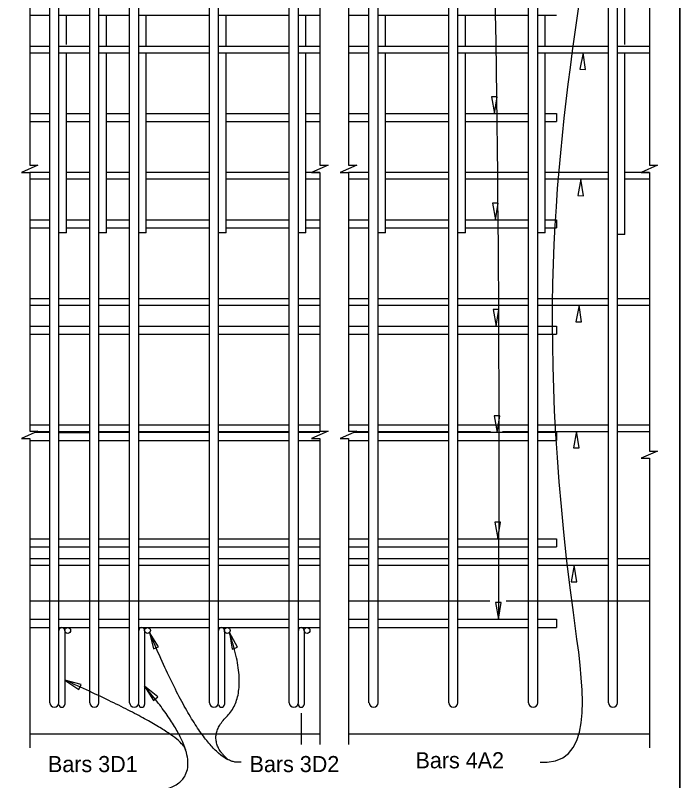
# Model space of a CAD drawing. Extents: x 0 to 20.5, y 0 to 12.9.
# Drawn here: x 16.322 to 20.485, y 4.445 to 9.244 of the extents above; entities that cross this region are included whole.
import ezdxf

# ---------------------------------------------------------------- set-up
doc = ezdxf.new("R2010")
doc.units = 0
for name, color, linetype in [('ActivePts-ConstElements', 7, 'Continuous'), ('BeamConc', 7, 'Continuous'), ('BeamConc_h', 7, 'Continuous'), ('Dimension', 7, 'Continuous'), ('Miscellaneous1', 7, 'Continuous'), ('Rebar', 7, 'Continuous'), ('TextStructures', 7, 'Continuous')]:
    doc.layers.add(name, color=color, linetype=linetype)

msp = doc.modelspace()

# ---------------------------------------------------------------- linework, layer by layer
at = {"layer": 'ActivePts-ConstElements'}
msp.add_lwpolyline([(-0.0403, -0.0256), (20.485, -0.0256), (20.485, 12.9475), (-0.0403, 12.9475)], close=True, dxfattribs=at)
at = {"layer": 'BeamConc'}
for p, q in [((16.4116, 4.739), (18.2295, 4.739)), ((18.4095, 4.739), (20.2953, 4.739))]:
    msp.add_line(p, q, dxfattribs=at)
at = {"layer": 'BeamConc_h'}
for p, q in [((16.4116, 5.5723), (18.2295, 5.5723)), ((18.4095, 5.5723), (19.2946, 5.5723)), ((19.3975, 5.5723), (20.2953, 5.5723))]:
    msp.add_line(p, q, dxfattribs=at)
at = {"layer": 'Dimension'}
msp.add_line((18.1135, 4.8686), (18.1135, 4.6717), dxfattribs=at)
for points in [[(16.4116, 10.0723), (16.4116, 8.3039), (16.4633, 8.3039), (16.36, 8.2589), (16.4116, 8.2589), (16.4116, 6.6365), (16.4633, 6.6365), (16.36, 6.5915), (16.4116, 6.5915), (16.4116, 4.6506)], [(18.2295, 10.0723), (18.2295, 8.3039), (18.2812, 8.3039), (18.1778, 8.2589), (18.2295, 8.2589), (18.2295, 6.6365), (18.2812, 6.6365), (18.1778, 6.5915), (18.2295, 6.5915), (18.2295, 4.6717)], [(18.4095, 10.0723), (18.4095, 8.3039), (18.4612, 8.3039), (18.3579, 8.2589), (18.4095, 8.2589), (18.4095, 6.6365), (18.4612, 6.6365), (18.3579, 6.5915), (18.4095, 6.5915), (18.4095, 4.6717)], [(20.2953, 10.0723), (20.2953, 8.3039), (20.347, 8.3039), (20.2437, 8.2589), (20.2953, 8.2589), (20.2953, 6.5115), (20.347, 6.5115), (20.2437, 6.4665), (20.2953, 6.4665), (20.2953, 4.6506)]]:
    msp.add_lwpolyline(points, dxfattribs=at)
for points in [[(19.8792, 9.0099), (19.8601, 8.906), (19.8953, 8.9055)], [(19.3235, 8.6296), (19.3404, 8.7339), (19.3051, 8.7336)], [(19.8656, 8.2178), (19.8465, 8.1139), (19.8818, 8.1134)], [(19.3313, 7.9628), (19.3482, 8.067), (19.3129, 8.0668)], [(19.3355, 7.2956), (19.3525, 7.3999), (19.3172, 7.3996)], [(19.8543, 7.4259), (19.8352, 7.3221), (19.8704, 7.3216)], [(19.3403, 6.6295), (19.3572, 6.7338), (19.322, 6.7335)], [(19.8387, 6.6364), (19.8196, 6.5325), (19.8549, 6.532)], [(19.3451, 5.9629), (19.362, 6.0671), (19.3267, 6.0669)], [(19.8246, 5.7963), (19.8055, 5.6925), (19.8408, 5.692)], [(19.3494, 5.4578), (19.3664, 5.562), (19.3311, 5.5618)], [(17.1629, 5.3745), (17.1867, 5.2716), (17.2193, 5.2852)], [(17.6629, 5.3745), (17.6802, 5.2703), (17.7135, 5.2818)], [(16.6318, 5.0758), (16.7197, 5.0172), (16.734, 5.0494)], [(17.1318, 5.0372), (17.1876, 4.9476), (17.214, 4.9709)]]:
    msp.add_lwpolyline(points, close=True, dxfattribs=at)
for points in [[(19.5169, 10.7039), (19.4625, 10.7051), (19.3121, 10.2105), (19.3494, 5.4578)], [(19.6115, 4.5619), (19.6547, 4.5619), (19.819, 5.4995), (19.8873, 9.5318)]]:
    msp.add_spline(points, degree=3, dxfattribs=at)
for points in [[(17.7362, 4.5622), (17.5173, 4.5252), (17.1629, 5.3745)], [(17.6567, 4.5757), (17.5049, 4.7071), (17.7938, 4.995), (17.6629, 5.3745)], [(17.3904, 4.6335), (17.3739, 4.7442), (16.6318, 5.0758)], [(17.0406, 4.3694), (17.7177, 4.3524), (17.1318, 5.0372)]]:
    msp.add_open_spline(points, degree=2, dxfattribs=at)
at = {"layer": 'Miscellaneous1'}
msp.add_lwpolyline([(0, 12.9475), (20.485, 12.9475), (20.485, 0), (0, 0)], close=True, dxfattribs=at)
at = {"layer": 'Rebar'}
for p, q in [((16.5953, 4.9343), (16.5953, 10.4187)), ((16.8453, 4.9343), (16.8453, 10.4187)), ((17.0953, 4.9343), (17.0953, 10.4187)), ((17.5953, 4.9343), (17.5953, 10.4187)), ((18.0953, 4.9343), (18.0953, 10.4187)), ((18.5953, 4.9343), (18.5953, 10.4187)), ((19.0953, 4.9343), (19.0953, 10.4187)), ((19.5953, 4.9343), (19.5953, 10.4187)), ((20.0953, 4.9343), (20.0953, 10.4187)), ((20.1422, 9.0619), (20.1422, 9.8475)), ((16.538, 4.9343), (16.538, 9.5318)), ((16.788, 4.9343), (16.788, 9.5318)), ((17.038, 4.9343), (17.038, 9.5318)), ((17.538, 4.9343), (17.538, 9.5318)), ((18.038, 4.9343), (18.038, 9.5318)), ((18.538, 4.9343), (18.538, 9.5318)), ((19.038, 4.9343), (19.038, 9.5318)), ((19.538, 4.9343), (19.538, 9.5318)), ((20.038, 4.9343), (20.038, 9.5318)), ((16.4116, 9.2443), (16.538, 9.2443)), ((16.5953, 9.2443), (16.788, 9.2443)), ((16.6422, 9.0619), (16.6422, 9.2443)), ((16.8453, 9.2443), (17.038, 9.2443)), ((16.8922, 9.0515), (16.8922, 9.2443)), ((17.0953, 9.2443), (17.538, 9.2443)), ((17.1422, 9.0515), (17.1422, 9.2443)), ((17.5953, 9.2443), (18.038, 9.2443)), ((17.6422, 9.0515), (17.6422, 9.2443)), ((18.0953, 9.2443), (18.2295, 9.2443)), ((18.1422, 9.0515), (18.1422, 9.2443)), ((18.4095, 9.2443), (18.538, 9.2443)), ((18.5953, 9.2443), (19.038, 9.2443)), ((18.6422, 9.0515), (18.6422, 9.2443)), ((19.0953, 9.2443), (19.538, 9.2443)), ((19.1422, 9.0515), (19.1422, 9.2443)), ((19.5953, 9.2443), (19.7125, 9.2443)), ((19.6422, 9.0515), (19.6422, 9.2443)), ((16.4116, 9.0515), (16.538, 9.0515)), ((16.5953, 9.0515), (16.788, 9.0515)), ((16.8453, 9.0515), (17.038, 9.0515)), ((17.0953, 9.0515), (17.538, 9.0515)), ((17.5953, 9.0515), (18.038, 9.0515)), ((18.0953, 9.0515), (18.2295, 9.0515)), ((18.4095, 9.0515), (18.538, 9.0515)), ((18.5953, 9.0515), (19.038, 9.0515)), ((19.0953, 9.0515), (19.538, 9.0515)), ((19.5953, 9.0515), (20.038, 9.0515)), ((20.0953, 9.0515), (20.2953, 9.0515)), ((16.4116, 9.0099), (16.538, 9.0099)), ((16.5953, 9.0099), (16.788, 9.0099)), ((16.6422, 7.8796), (16.6422, 9.0099)), ((16.8453, 9.0099), (17.038, 9.0099)), ((16.8922, 7.8796), (16.8922, 9.0099)), ((17.0953, 9.0099), (17.538, 9.0099)), ((17.1422, 7.8796), (17.1422, 9.0099)), ((17.5953, 9.0099), (18.038, 9.0099)), ((17.6422, 7.8796), (17.6422, 9.0099)), ((18.0953, 9.0099), (18.2295, 9.0099)), ((18.1422, 7.8796), (18.1422, 9.0099)), ((18.4095, 9.0099), (18.538, 9.0099)), ((18.5953, 9.0099), (19.038, 9.0099)), ((18.6422, 7.8796), (18.6422, 9.0099)), ((19.0953, 9.0099), (19.538, 9.0099)), ((19.1422, 7.8796), (19.1422, 9.0099)), ((19.5953, 9.0099), (20.038, 9.0099)), ((19.6422, 7.8796), (19.6422, 9.0099)), ((20.0953, 9.0099), (20.2953, 9.0099)), ((20.1422, 7.8692), (20.1422, 9.0099)), ((16.4116, 8.6296), (16.538, 8.6296)), ((16.6422, 8.6296), (16.788, 8.6296)), ((16.8922, 8.6296), (17.038, 8.6296)), ((17.1422, 8.6296), (17.538, 8.6296)), ((17.6422, 8.6296), (18.038, 8.6296)), ((18.1422, 8.6296), (18.2295, 8.6296)), ((18.4095, 8.6296), (18.538, 8.6296)), ((18.6422, 8.6296), (19.038, 8.6296)), ((19.1422, 8.6296), (19.538, 8.6296)), ((19.6422, 8.6296), (19.7125, 8.6296)), ((19.7125, 8.6296), (19.7125, 8.5776)), ((16.4116, 8.5776), (16.538, 8.5776)), ((16.6422, 8.5776), (16.788, 8.5776)), ((16.8922, 8.5776), (17.038, 8.5776)), ((17.1422, 8.5776), (17.538, 8.5776)), ((17.6422, 8.5776), (18.038, 8.5776)), ((18.1422, 8.5776), (18.2295, 8.5776)), ((18.4095, 8.5776), (18.538, 8.5776)), ((18.6422, 8.5776), (19.038, 8.5776)), ((19.1422, 8.5776), (19.538, 8.5776)), ((19.6422, 8.5776), (19.7125, 8.5776)), ((16.4116, 8.2598), (16.538, 8.2598)), ((16.6422, 8.2598), (16.788, 8.2598)), ((16.8922, 8.2598), (17.038, 8.2598)), ((17.1422, 8.2598), (17.538, 8.2598)), ((17.6422, 8.2598), (18.038, 8.2598)), ((18.1422, 8.2598), (18.2295, 8.2598)), ((18.4095, 8.2598), (18.538, 8.2598)), ((18.6422, 8.2598), (19.038, 8.2598)), ((19.1422, 8.2598), (19.538, 8.2598)), ((19.6422, 8.2598), (20.038, 8.2598)), ((20.1422, 8.2598), (20.2953, 8.2598)), ((16.4116, 8.2182), (16.538, 8.2182)), ((16.6422, 8.2182), (16.788, 8.2182)), ((16.8922, 8.2182), (17.038, 8.2182)), ((17.1422, 8.2182), (17.538, 8.2182)), ((17.6422, 8.2182), (18.038, 8.2182)), ((18.1422, 8.2182), (18.2295, 8.2182)), ((18.4095, 8.2182), (18.538, 8.2182)), ((18.6422, 8.2182), (19.038, 8.2182)), ((19.1422, 8.2182), (19.538, 8.2182)), ((19.6422, 8.2182), (20.038, 8.2182)), ((20.1422, 8.2182), (20.2953, 8.2182)), ((16.4116, 7.9629), (16.538, 7.9629)), ((16.6422, 7.9629), (16.788, 7.9629)), ((16.8922, 7.9629), (17.038, 7.9629)), ((17.1422, 7.9629), (17.538, 7.9629)), ((17.6422, 7.9629), (18.038, 7.9629)), ((18.1422, 7.9629), (18.2295, 7.9629)), ((18.4095, 7.9629), (18.538, 7.9629)), ((18.6422, 7.9629), (19.038, 7.9629)), ((19.1422, 7.9629), (19.538, 7.9629)), ((19.6422, 7.9629), (19.7125, 7.9629)), ((19.7125, 7.9629), (19.7125, 7.9109)), ((16.4116, 7.9109), (16.538, 7.9109)), ((16.6422, 7.8796), (16.5953, 7.8796)), ((16.6422, 7.9109), (16.788, 7.9109)), ((16.8922, 7.8796), (16.8453, 7.8796)), ((16.8922, 7.9109), (17.038, 7.9109)), ((17.1422, 7.8796), (17.0953, 7.8796)), ((17.1422, 7.9109), (17.538, 7.9109)), ((17.6422, 7.8796), (17.5953, 7.8796)), ((17.6422, 7.9109), (18.038, 7.9109)), ((18.1422, 7.8796), (18.0953, 7.8796)), ((18.1422, 7.9109), (18.2295, 7.9109)), ((18.4095, 7.9109), (18.538, 7.9109)), ((18.6422, 7.8796), (18.5953, 7.8796)), ((18.6422, 7.9109), (19.038, 7.9109)), ((19.1422, 7.8796), (19.0953, 7.8796)), ((19.1422, 7.9109), (19.538, 7.9109)), ((19.6422, 7.8796), (19.5953, 7.8796)), ((19.6422, 7.9109), (19.7125, 7.9109)), ((20.1422, 7.8692), (20.0953, 7.8692)), ((16.4116, 7.4681), (16.538, 7.4681)), ((16.5953, 7.4681), (16.788, 7.4681)), ((16.8453, 7.4681), (17.038, 7.4681)), ((17.0953, 7.4681), (17.538, 7.4681)), ((17.5953, 7.4681), (18.038, 7.4681)), ((18.0953, 7.4681), (18.2295, 7.4681)), ((18.4095, 7.4681), (18.538, 7.4681)), ((18.5953, 7.4681), (19.038, 7.4681)), ((19.0953, 7.4681), (19.538, 7.4681)), ((19.5953, 7.4681), (20.038, 7.4681)), ((20.0953, 7.4681), (20.2953, 7.4681)), ((16.4116, 7.4265), (16.538, 7.4265)), ((16.5953, 7.4265), (16.788, 7.4265)), ((16.8453, 7.4265), (17.038, 7.4265)), ((17.0953, 7.4265), (17.538, 7.4265)), ((17.5953, 7.4265), (18.038, 7.4265)), ((18.0953, 7.4265), (18.2295, 7.4265)), ((18.4095, 7.4265), (18.538, 7.4265)), ((18.5953, 7.4265), (19.038, 7.4265)), ((19.0953, 7.4265), (19.538, 7.4265)), ((19.5953, 7.4265), (20.038, 7.4265)), ((20.0953, 7.4265), (20.2953, 7.4265)), ((16.4116, 7.2962), (16.538, 7.2962)), ((16.5953, 7.2962), (16.788, 7.2962)), ((16.8453, 7.2962), (17.038, 7.2962)), ((17.0953, 7.2962), (17.538, 7.2962)), ((17.5953, 7.2962), (18.038, 7.2962)), ((18.0953, 7.2962), (18.2295, 7.2962)), ((18.4095, 7.2962), (18.538, 7.2962)), ((18.5953, 7.2962), (19.038, 7.2962)), ((19.0953, 7.2962), (19.538, 7.2962)), ((19.5953, 7.2962), (19.7125, 7.2962)), ((19.7125, 7.2962), (19.7125, 7.2442)), ((16.4116, 7.2442), (16.538, 7.2442)), ((16.5953, 7.2442), (16.788, 7.2442)), ((16.8453, 7.2442), (17.038, 7.2442)), ((17.0953, 7.2442), (17.538, 7.2442)), ((17.5953, 7.2442), (18.038, 7.2442)), ((18.0953, 7.2442), (18.2295, 7.2442)), ((18.4095, 7.2442), (18.538, 7.2442)), ((18.5953, 7.2442), (19.038, 7.2442)), ((19.0953, 7.2442), (19.538, 7.2442)), ((19.5953, 7.2442), (19.7125, 7.2442)), ((16.4116, 6.6764), (16.538, 6.6764)), ((16.5953, 6.6764), (16.788, 6.6764)), ((16.8453, 6.6764), (17.038, 6.6764)), ((17.0953, 6.6764), (17.538, 6.6764)), ((17.5953, 6.6764), (18.038, 6.6764)), ((18.0953, 6.6764), (18.2295, 6.6764)), ((18.4095, 6.6764), (18.538, 6.6764)), ((18.5953, 6.6764), (19.038, 6.6764)), ((19.0953, 6.6764), (19.538, 6.6764)), ((19.5953, 6.6764), (20.038, 6.6764)), ((20.0953, 6.6764), (20.2953, 6.6764)), ((16.449, 6.6296), (16.538, 6.6296)), ((16.4603, 6.6348), (16.538, 6.6348)), ((16.5953, 6.6348), (16.788, 6.6348)), ((16.5953, 6.6295), (16.788, 6.6295)), ((16.8453, 6.6348), (17.038, 6.6348)), ((16.8453, 6.6296), (17.038, 6.6296)), ((17.0953, 6.6348), (17.538, 6.6348)), ((17.0953, 6.6296), (17.538, 6.6296)), ((17.5953, 6.6348), (18.038, 6.6348)), ((17.5953, 6.6296), (18.038, 6.6296)), ((18.0953, 6.6348), (18.2295, 6.6348)), ((18.0953, 6.6296), (18.2295, 6.6296)), ((18.447, 6.6296), (18.538, 6.6296)), ((18.4582, 6.6348), (18.538, 6.6348)), ((18.5953, 6.6348), (19.038, 6.6348)), ((18.5953, 6.6296), (19.038, 6.6296)), ((19.0953, 6.6348), (19.2997, 6.6348)), ((19.0953, 6.6296), (19.538, 6.6296)), ((19.3742, 6.6348), (19.538, 6.6348)), ((19.5953, 6.6348), (20.038, 6.6348)), ((19.5953, 6.6296), (19.7125, 6.6296)), ((19.7125, 6.6296), (19.7125, 6.5775)), ((20.0953, 6.6348), (20.2953, 6.6348)), ((16.4116, 6.5774), (16.538, 6.5774)), ((16.5953, 6.5775), (16.788, 6.5775)), ((16.8453, 6.5775), (17.038, 6.5775)), ((17.0953, 6.5775), (17.538, 6.5775)), ((17.5953, 6.5775), (18.038, 6.5775)), ((18.0953, 6.5775), (18.2295, 6.5775)), ((18.4095, 6.5775), (18.538, 6.5775)), ((18.5953, 6.5775), (19.038, 6.5775)), ((19.0953, 6.5775), (19.538, 6.5775)), ((19.5953, 6.5775), (19.7125, 6.5775)), ((16.4116, 5.9628), (16.538, 5.9628)), ((16.5953, 5.9628), (16.788, 5.9628)), ((16.8453, 5.9628), (17.038, 5.9628)), ((17.0953, 5.9628), (17.538, 5.9628)), ((17.5953, 5.9628), (18.038, 5.9628)), ((18.0953, 5.9628), (18.2295, 5.9628)), ((18.4095, 5.9628), (18.538, 5.9628)), ((18.5953, 5.9628), (19.038, 5.9628)), ((19.0953, 5.9628), (19.538, 5.9628)), ((19.5953, 5.9628), (19.7125, 5.9628)), ((19.7125, 5.9628), (19.7125, 5.9108)), ((16.4116, 5.9108), (16.538, 5.9108)), ((16.5953, 5.9108), (16.788, 5.9108)), ((16.8453, 5.9108), (17.038, 5.9108)), ((17.0953, 5.9108), (17.538, 5.9108)), ((17.5953, 5.9108), (18.038, 5.9108)), ((18.0953, 5.9108), (18.2295, 5.9108)), ((18.4095, 5.9108), (18.538, 5.9108)), ((18.5953, 5.9108), (19.038, 5.9108)), ((19.0953, 5.9108), (19.538, 5.9108)), ((19.5953, 5.9108), (19.7125, 5.9108)), ((16.4116, 5.838), (16.538, 5.838)), ((16.5953, 5.838), (16.788, 5.838)), ((16.8453, 5.838), (17.038, 5.838)), ((17.0953, 5.838), (17.538, 5.838)), ((17.5953, 5.838), (18.038, 5.838)), ((18.0953, 5.838), (18.2295, 5.838)), ((18.4095, 5.838), (18.538, 5.838)), ((18.5953, 5.838), (19.038, 5.838)), ((19.0953, 5.838), (19.538, 5.838)), ((19.5953, 5.838), (20.038, 5.838)), ((20.0953, 5.838), (20.2953, 5.838)), ((16.4116, 5.7963), (16.538, 5.7963)), ((16.5953, 5.7963), (16.788, 5.7963)), ((16.8453, 5.7963), (17.038, 5.7963)), ((17.0953, 5.7963), (17.538, 5.7963)), ((17.5953, 5.7963), (18.038, 5.7963)), ((18.0953, 5.7963), (18.2295, 5.7963)), ((18.4095, 5.7963), (18.538, 5.7963)), ((18.5953, 5.7963), (19.038, 5.7963)), ((19.0953, 5.7963), (19.538, 5.7963)), ((19.5953, 5.7963), (20.038, 5.7963)), ((20.0953, 5.7963), (20.2953, 5.7963)), ((16.4116, 5.4577), (16.538, 5.4577)), ((16.5953, 5.4577), (16.788, 5.4577)), ((16.8453, 5.4577), (17.038, 5.4577)), ((17.0953, 5.4577), (17.538, 5.4577)), ((17.5953, 5.4577), (18.038, 5.4577)), ((18.0953, 5.4577), (18.2295, 5.4577)), ((18.4095, 5.4577), (18.538, 5.4577)), ((18.5953, 5.4577), (19.038, 5.4577)), ((19.0953, 5.4577), (19.538, 5.4577)), ((19.5953, 5.4577), (19.7125, 5.4577)), ((19.7125, 5.4577), (19.7125, 5.4057)), ((16.4116, 5.4057), (16.538, 5.4057)), ((16.5953, 5.4057), (16.788, 5.4057)), ((16.6318, 5.3874), (16.6318, 4.9239)), ((16.8453, 5.4057), (17.038, 5.4057)), ((17.0953, 5.4057), (17.538, 5.4057)), ((17.1318, 5.3874), (17.1318, 4.9239)), ((17.5953, 5.4057), (18.038, 5.4057)), ((17.6318, 5.3874), (17.6318, 4.9239)), ((18.0953, 5.4057), (18.2295, 5.4057)), ((18.1318, 5.3874), (18.1318, 4.9239)), ((18.4095, 5.4057), (18.538, 5.4057)), ((18.5953, 5.4057), (19.038, 5.4057)), ((19.0953, 5.4057), (19.538, 5.4057)), ((19.5953, 5.4057), (19.7125, 5.4057))]:
    msp.add_line(p, q, dxfattribs=at)
for centre in [(16.65, 5.3874), (17.15, 5.3874), (17.65, 5.3874), (18.15, 5.3874)]:
    msp.add_circle(centre, 0.0182, dxfattribs=at)
for centre, radius, start, end in [((16.6135, 5.3874), 0.0182, 0, 180), ((17.1135, 5.3874), 0.0182, 0, 180), ((17.6135, 5.3874), 0.0182, 0, 180), ((18.1135, 5.3874), 0.0182, 0, 180), ((16.5667, 4.9343), 0.0286, 180, 0), ((16.6135, 4.9239), 0.0182, 180, 0), ((16.8167, 4.9343), 0.0286, 180, 0), ((17.0667, 4.9343), 0.0286, 180, 0), ((17.1135, 4.9239), 0.0182, 180, 0), ((17.5667, 4.9343), 0.0286, 180, 0), ((17.6135, 4.9239), 0.0182, 180, 0), ((18.0667, 4.9343), 0.0286, 180, 0), ((18.1135, 4.9239), 0.0182, 180, 0), ((18.5667, 4.9343), 0.0286, 180, 0), ((19.0667, 4.9343), 0.0286, 180, 0), ((19.5667, 4.9343), 0.0286, 180, 0), ((20.0667, 4.9343), 0.0286, 180, 0)]:
    msp.add_arc(centre, radius, start, end, dxfattribs=at)

# ---------------------------------------------------------------- texts
at = {"layer": 'Dimension'}
for s, p in [('Bars 3D1 ', (16.5264, 4.4992)), ('Bars 3D2 ', (17.7898, 4.4992))]:
    msp.add_text(s, height=0.1008, dxfattribs=at).set_placement(p)
at = {"layer": 'TextStructures'}
msp.add_text('Bars 4A2', height=0.1008, dxfattribs=at).set_placement((18.8297, 4.5229))

doc.saveas('drawing.dxf')
